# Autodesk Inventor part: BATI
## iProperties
Shininess: 64.0
Length Units: 11269
Angle Units: 11279
Time Units: 11290
Mass Units: 11283
Length Display Precision: 3
Angle Display Precision: 2
Compacted: True
Part Number: BATI
Document SubType Name: Modeling
Created: 2004-07
Material: Par défaut
Designer: Sophie
Density: 1 g/cm^3
Density: 0.0
Volumn: 0.0
Area: 0.0
PropertySet Name: Model Information
Control State: 0
Master: False
Checked Out: False
Author: Sophie
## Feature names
1. Extrusion1
2. Congé1 [Fillet]
3. Congé2 [Fillet]
4. Extrusion2
5. Extrusion3
6. Congé3 [Fillet]
7. Perçage1 [Hole]
8. Extrusion4
9. Perçage2 [Hole]
10. Perçage3 [Hole]
11. Extrusion5
12. Extrusion6
13. Congé4 [Fillet]
14. Congé5 [Fillet]
15. Congé9 [Fillet]
16. Congé10 [Fillet]
17. Congé11 [Fillet]
18. Perçage4 [Hole]
19. Extrusion7
20. Congé12 [Fillet]
21. Congé13 [Fillet]
22. Extrusion8
23. Congé14 [Fillet]
24. Symétrie1 [Mirror]
25. Extrusion9
26. Congé15 [Fillet]
27. Extrusion10
28. Congé16 [Fillet]
29. Congé17 [Fillet]
30. Symétrie2 [Mirror]
31. Symétrie3 [Mirror]
32. Perçage5 [Hole]
33. Chanfrein1 [Chamfer]
34. Symétrie4 [Mirror]
35. Perçage6 [Hole]
36. Symétrie5 [Mirror]
37. Extrusion11
38. Perçage7 [Hole]
39. Congé18 [Fillet]
40. Congé19 [Fillet]
41. Congé20 [Fillet]
42. Congé22 [Fillet]
43. Congé23 [Fillet]
44. Symétrie6 [Mirror]
45. Congé24 [Fillet]
46. Congé25 [Fillet]
47. Congé26 [Fillet]
48. Congé27 [Fillet]
49. Congé28 [Fillet]
50. Congé29 [Fillet]
51. Congé30 [Fillet]
52. Congé33 [Fillet]
53. Congé34 [Fillet]
54. Congé36 [Fillet]
55. Congé37 [Fillet]
56. Congé38 [Fillet]
57. Congé39 [Fillet]
58. Congé40 [Fillet]
59. Extrusion12
60. Perçage8 [Hole]
61. Perçage9 [Hole]
62. Extrusion13
63. Extrusion14
64. Extrusion15
